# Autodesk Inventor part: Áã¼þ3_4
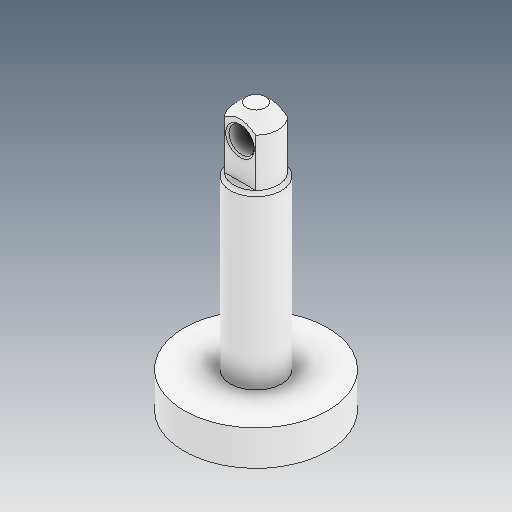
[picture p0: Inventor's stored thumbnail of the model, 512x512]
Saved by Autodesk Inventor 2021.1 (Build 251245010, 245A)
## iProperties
Created: 2021-05
Part Number: Áã¼þ3_4
Material: Ogólny
Document SubType Name: Modeling
Designer: user
Density: 1 g/cm^3
Appearance: Domyślna
Author: user
Revision Number: ÈÎºÎ
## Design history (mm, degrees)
feature "ÊäÈë1"
node "Bryła1"
